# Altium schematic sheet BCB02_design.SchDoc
size 513 x 386 mm
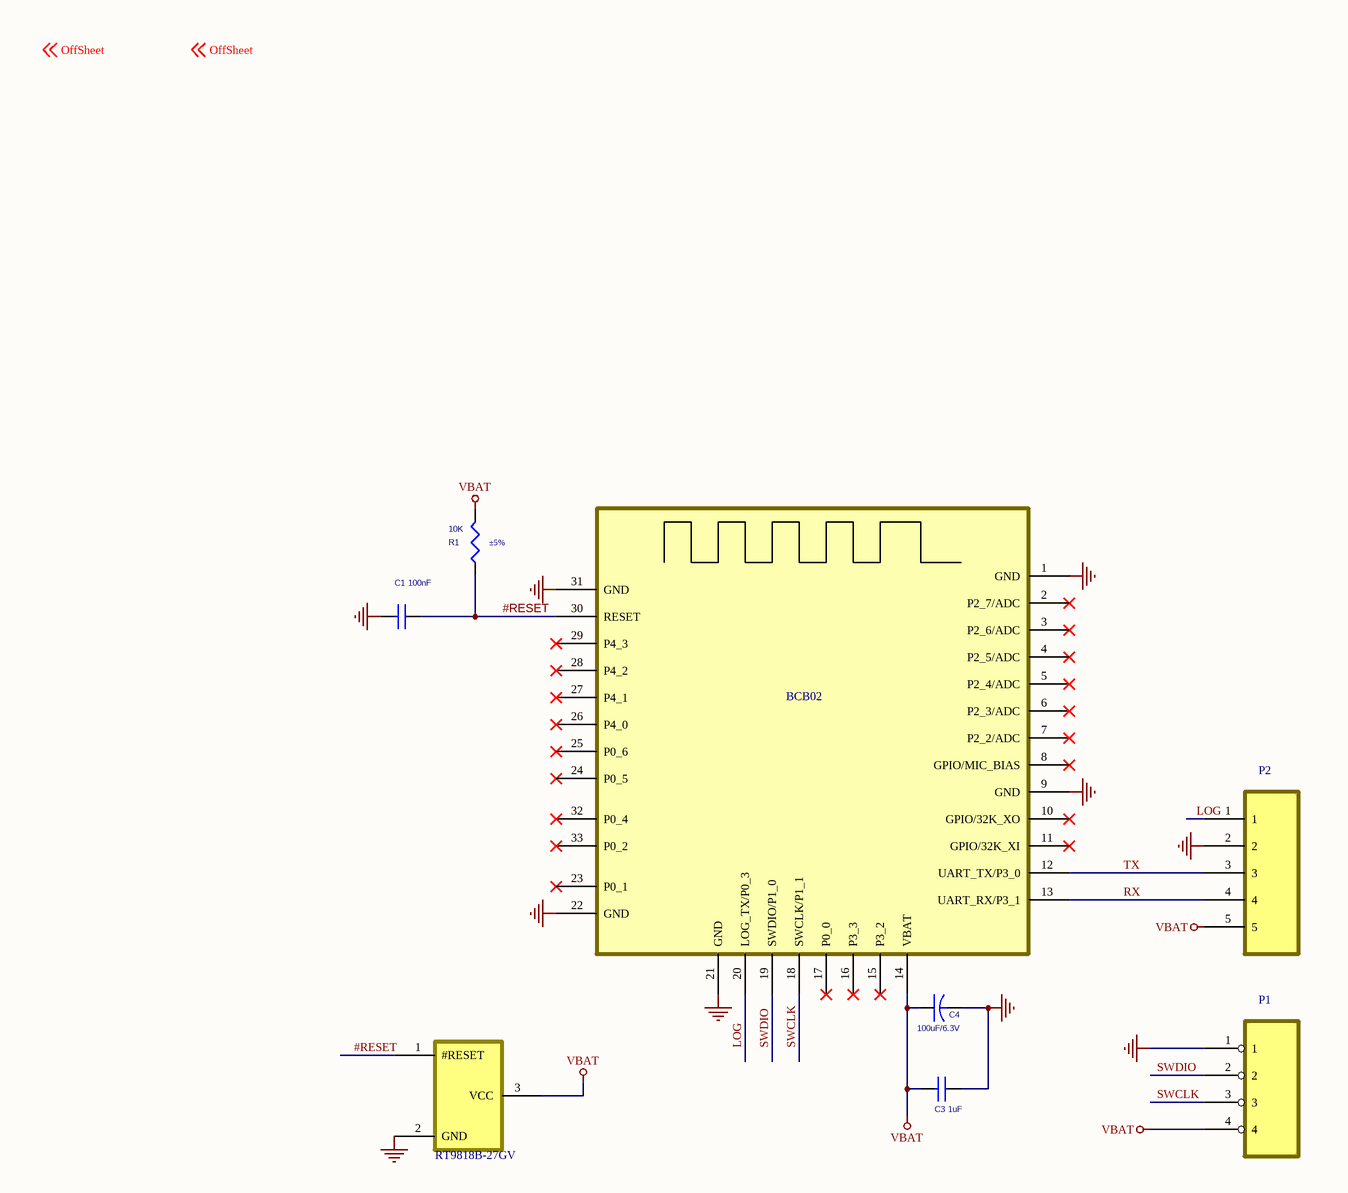
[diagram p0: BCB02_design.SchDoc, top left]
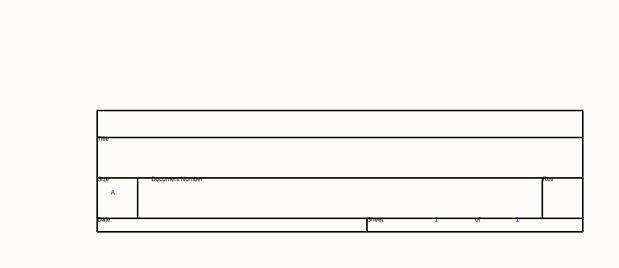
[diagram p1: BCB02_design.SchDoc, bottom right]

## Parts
(Parts that share a designator on the sheet are numbered #1, #2 ... from top to bottom, then left to right.)
*#1  RT9818B-27GV  (mechanical)
*#2  Page Size: A  Page Number: 1  (hidden comment: TitleBlock0)  (graphical)
BCB02  BCB02  [Model]
C1  100nF  [C0402]
C3  1uF  [C0402]
C4  100uF/6.3V  [0603C]
P1  *  (value not drawn)
P2  *  (value not drawn)
R1  10K  Tolerance: ±5%  [X0402R_3D]

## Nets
GND: *#1.2(GND) BCB02.1(GND) BCB02.9(GND) BCB02.21(GND) BCB02.22(GND) BCB02.31(GND) C1.2 C3.1 C4.2 P1.1 P2.2
VBAT: *#1.3(VCC) BCB02.14(VBAT) C3.2 C4.1 P1.4 P2.5 R1.2(R1B)
#RESET: *#1.1(#RESET) BCB02.30(RESET) C1.1 R1.1(R1A)
LOG: BCB02.20(LOG_TX/P0_3) P2.1
RX: BCB02.13(UART_RX/P3_1) P2.4
SWCLK: BCB02.18(SWCLK/P1_1) P1.3
SWDIO: BCB02.19(SWDIO/P1_0) P1.2
TX: BCB02.12(UART_TX/P3_0) P2.3

Not connected (* = marked no-connect by the designer): BCB02 2(P2_7/ADC)* 3(P2_6/ADC)* 4(P2_5/ADC)* 5(P2_4/ADC)* 6(P2_3/ADC)* 7(P2_2/ADC)* 8(GPIO/MIC_BIAS)* 10(GPIO/32K_XO)* 11(GPIO/32K_XI)* 15(P3_2)* 16(P3_3)* 17(P0_0)* 23(P0_1)* 24(P0_5)* 25(P0_6)* 26(P4_0)* 27(P4_1)* 28(P4_2)* 29(P4_3)* 32(P0_4)* 33(P0_2)*

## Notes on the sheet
- Labels drawn without touching a wire or pin: OffSheet

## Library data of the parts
BCB02 = BCB01
C1 C3 = CAP NP_Dup1
C4 = CAP: CISPartType: Capacitor\1206; ATHEROS KEY: 034-226CK-004; AtherosDescription: CAP,1206,X5R,22uF,+/-10%,25V; Voltage: 16V; Tolerance: +/-10%
P1 P2 = Component_1
R1 = RES: Power Ratingat: 1/8W; MaxWorkingVoltage: 50V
